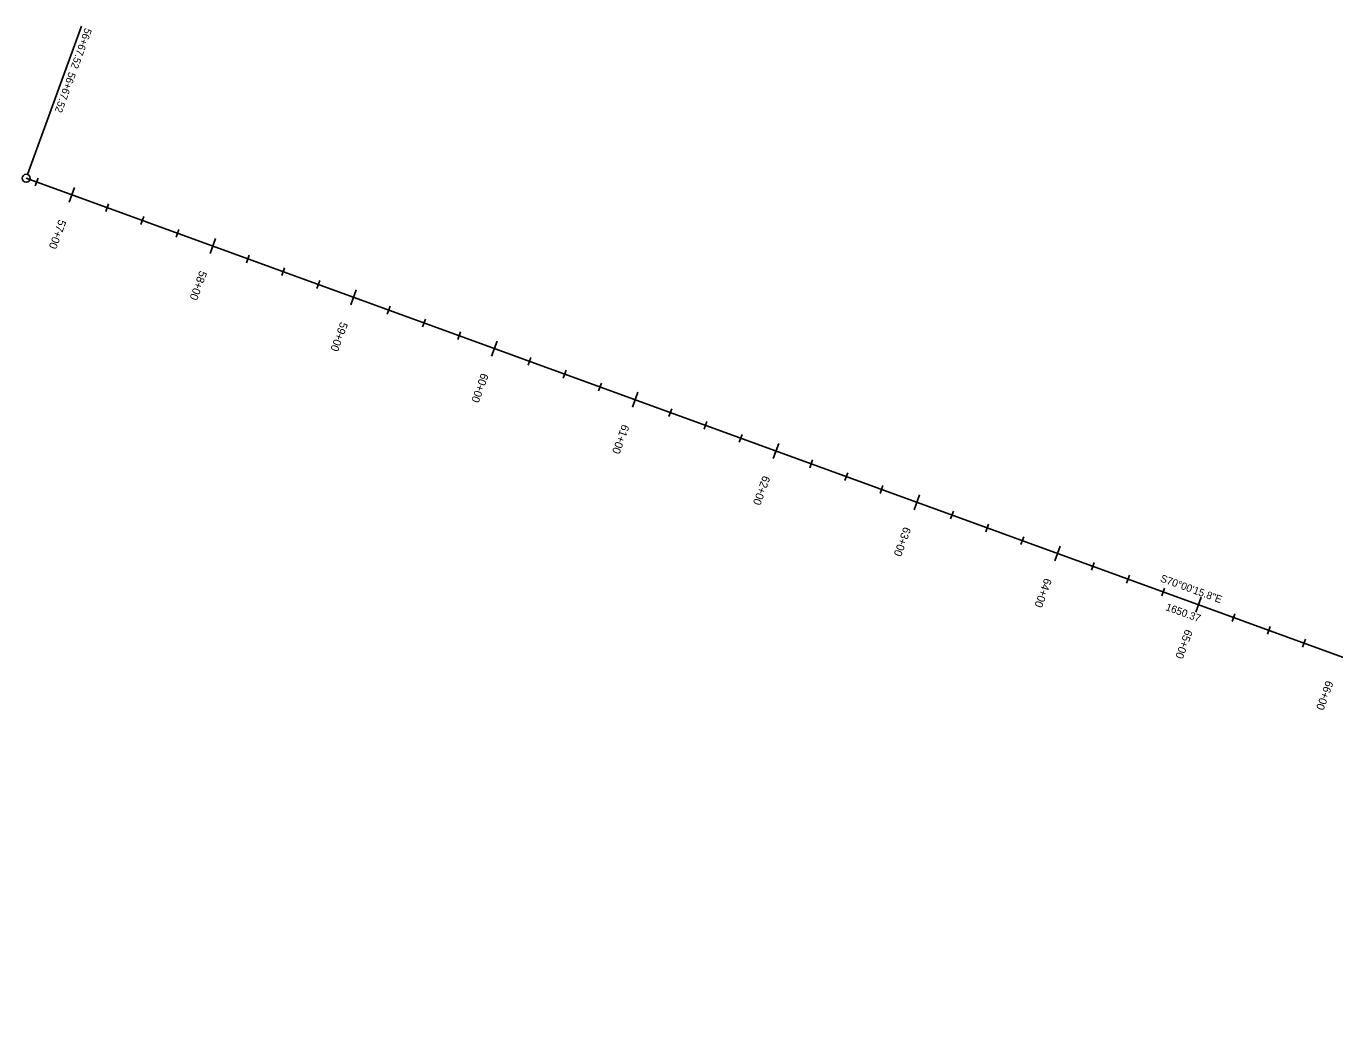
# Model space of a CAD drawing. Extents: x 2301963 to 2307911, y 760768 to 761974.
# Drawn here: x 2302574 to 2303447, y 761026 to 761692 of the extents above; entities that cross this region are included whole.
import ezdxf

# ---------------------------------------------------------------- set-up
doc = ezdxf.new("R2010")
doc.units = 0
for name, color, linetype in [('Default', 7, 'Continuous'), ('Draft_Bearing Label', 7, 'Continuous'), ('Draft_Station Cardinal Lines', 7, 'Continuous'), ('Draft_Station Cardinal Points', 7, 'Continuous'), ('Draft_Station Labels Major', 7, 'Continuous'), ('Draft_Station Ticks Major', 7, 'Continuous'), ('Draft_Station Ticks Minor', 7, 'Continuous'), ('Geom_Secondary', 7, 'Continuous')]:
    doc.layers.add(name, color=color, linetype=linetype)

msp = doc.modelspace()

# ---------------------------------------------------------------- linework, layer by layer
at = {"layer": 'Default'}
msp.add_line((2302574.09, 761590.06), (2304124.97, 761025.72), dxfattribs=at)
at = {"layer": 'Draft_Station Cardinal Lines'}
msp.add_line((2302575, 761592.57), (2302611.02, 761691.55), dxfattribs=at)
at = {"layer": 'Draft_Station Cardinal Points'}
for p, q in [((2302611.02, 761691.55), (2302611.02, 761691.55)), ((2302574.09, 761590.06), (2302574.09, 761590.06))]:
    msp.add_line(p, q, dxfattribs=at)
msp.add_circle((2302574.09, 761590.06), 2.67, dxfattribs=at)
at = {"layer": 'Draft_Station Ticks Major'}
for p, q in [((2302606.44, 761583.97), (2302602.81, 761574)), ((2302700.41, 761549.78), (2302696.78, 761539.8)), ((2302794.38, 761515.59), (2302790.75, 761505.61)), ((2302888.35, 761481.39), (2302884.72, 761471.41)), ((2302982.32, 761447.2), (2302978.69, 761437.22)), ((2303076.3, 761413), (2303072.66, 761403.02)), ((2303170.27, 761378.81), (2303166.64, 761368.83)), ((2303264.24, 761344.61), (2303260.61, 761334.63)), ((2303358.21, 761310.42), (2303354.58, 761300.44))]:
    msp.add_line(p, q, dxfattribs=at)
at = {"layer": 'Draft_Station Ticks Minor'}
for p, q in [((2302582.06, 761590.1), (2302580.17, 761584.91)), ((2302629.05, 761573), (2302627.16, 761567.81)), ((2302652.54, 761564.45), (2302650.65, 761559.27)), ((2302676.03, 761555.9), (2302674.15, 761550.72)), ((2302723.02, 761538.81), (2302721.13, 761533.62)), ((2302746.51, 761530.26), (2302744.62, 761525.07)), ((2302770.01, 761521.71), (2302768.12, 761516.52)), ((2302816.99, 761504.61), (2302815.1, 761499.42)), ((2302840.48, 761496.06), (2302838.6, 761490.88)), ((2302863.98, 761487.51), (2302862.09, 761482.33)), ((2302910.96, 761470.42), (2302909.08, 761465.23)), ((2302934.46, 761461.87), (2302932.57, 761456.68)), ((2302957.95, 761453.32), (2302956.06, 761448.13)), ((2303004.93, 761436.22), (2303003.05, 761431.04)), ((2303028.43, 761427.67), (2303026.54, 761422.49)), ((2303051.92, 761419.13), (2303050.03, 761413.94)), ((2303098.91, 761402.03), (2303097.02, 761396.84)), ((2303122.4, 761393.48), (2303120.51, 761388.29)), ((2303145.89, 761384.93), (2303144.01, 761379.74)), ((2303192.88, 761367.83), (2303190.99, 761362.65)), ((2303216.37, 761359.28), (2303214.48, 761354.1)), ((2303239.86, 761350.74), (2303237.98, 761345.55)), ((2303286.85, 761333.64), (2303284.96, 761328.45)), ((2303310.34, 761325.09), (2303308.46, 761319.9)), ((2303333.84, 761316.54), (2303331.95, 761311.35)), ((2303380.82, 761299.44), (2303378.93, 761294.26)), ((2303404.32, 761290.89), (2303402.43, 761285.71)), ((2303427.81, 761282.35), (2303425.92, 761277.16))]:
    msp.add_line(p, q, dxfattribs=at)
at = {"layer": 'Geom_Secondary'}
msp.add_line((2302574.09, 761590.06), (2304124.97, 761025.72), dxfattribs=at)

# ---------------------------------------------------------------- texts
at = {"layer": 'Draft_Bearing Label'}
for s, p in [('S70°00\'15.8"E', (2303330.55, 761321.06)), ('1650.37', (2303334.1, 761301.93))]:
    msp.add_text(s, height=5, rotation=340.00439, dxfattribs=at).set_placement(p)
at = {"layer": 'Draft_Station Cardinal Points'}
for p in [(2302613.36, 761690.7), (2302602.67, 761661.33)]:
    msp.add_text('56+67.52', height=5, rotation=250.00439, dxfattribs=at).set_placement(p)
at = {"layer": 'Draft_Station Labels Major'}
for s, p in [('57+00', (2302595.95, 761562.95)), ('58+00', (2302689.92, 761528.76)), ('59+00', (2302783.89, 761494.57)), ('60+00', (2302877.86, 761460.37)), ('61+00', (2302971.83, 761426.18)), ('62+00', (2303065.81, 761391.98)), ('63+00', (2303159.78, 761357.79)), ('64+00', (2303253.75, 761323.59)), ('65+00', (2303347.72, 761289.4)), ('66+00', (2303441.69, 761255.2))]:
    msp.add_text(s, height=5.34, rotation=250.00439, dxfattribs=at).set_placement(p)

doc.saveas('drawing.dxf')
